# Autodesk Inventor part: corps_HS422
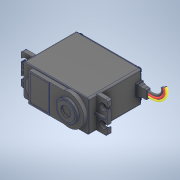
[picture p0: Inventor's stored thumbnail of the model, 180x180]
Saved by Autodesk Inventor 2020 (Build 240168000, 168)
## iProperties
Created: 2012-04
Part Number: corps_HS422
Material: Générique
Document SubType Name: Modeling
Designer: bruno
Density: 1 g/cm^3
Appearance: Par défaut
Author: bruno
Sending System: SolidWorks 2016
Last Author: Prof
Last Saved: 2018-11-12
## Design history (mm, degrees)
feature "Symétrie4"
node "Solide1"
